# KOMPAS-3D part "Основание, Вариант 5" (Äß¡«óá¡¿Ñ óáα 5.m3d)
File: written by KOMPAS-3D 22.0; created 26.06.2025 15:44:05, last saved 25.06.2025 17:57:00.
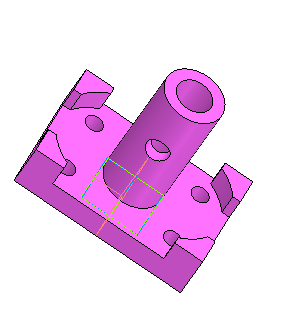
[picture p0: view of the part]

Document properties: Автор: Helen; Полное имя файла: D:\MY\WORK\MPEI\ППЭ_2025-2026\Варианты\Вар 5 СБ\Основание вар 5.m3d

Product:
- Body: Тело 1
    Масса: 4.091939
- Part/product: Основание  | designation Вариант 5
    Масса: 3.438966

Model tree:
1. Эскиз:1
2. Элемент выдавливания:1
     Расстояние 1 = 20
3. Эскиз:2  (with: Элемент выдавливания:1)
4. Элемент выдавливания:2
     Расстояние 1 = 20
5. Зеркальный массив:1
6. Экземпляр ( 1 )
7. Экземпляр ( 2 )  (with: Элемент выдавливания:2)
8. Зеркальный массив:2  (with: Экземпляр ( 1 ), Экземпляр ( 2 ), Зеркальный массив:1, Элемент выдавливания:2)
9. Эскиз:3  (with: Элемент выдавливания:1)
10. Элемент выдавливания:3
11. Зеркальный массив:3  (with: Экземпляр ( 1 ), Экземпляр ( 2 ), Элемент выдавливания:3)
12. Зеркальный массив:4  (with: Экземпляр ( 1 ), Экземпляр ( 2 ), Зеркальный массив:3, Элемент выдавливания:3)
13. Эскиз:4  (with: Элемент выдавливания:1)
14. Элемент выдавливания:4
     Расстояние 1 = 110
15. Эскиз:5  (with: Элемент выдавливания:1)
16. Элемент выдавливания:5
     Расстояние 1 = 50
17. Эскиз:6  (with: Элемент выдавливания:4)
18. Элемент выдавливания:6
     Расстояние 2 = 130

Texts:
  Вариант 5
